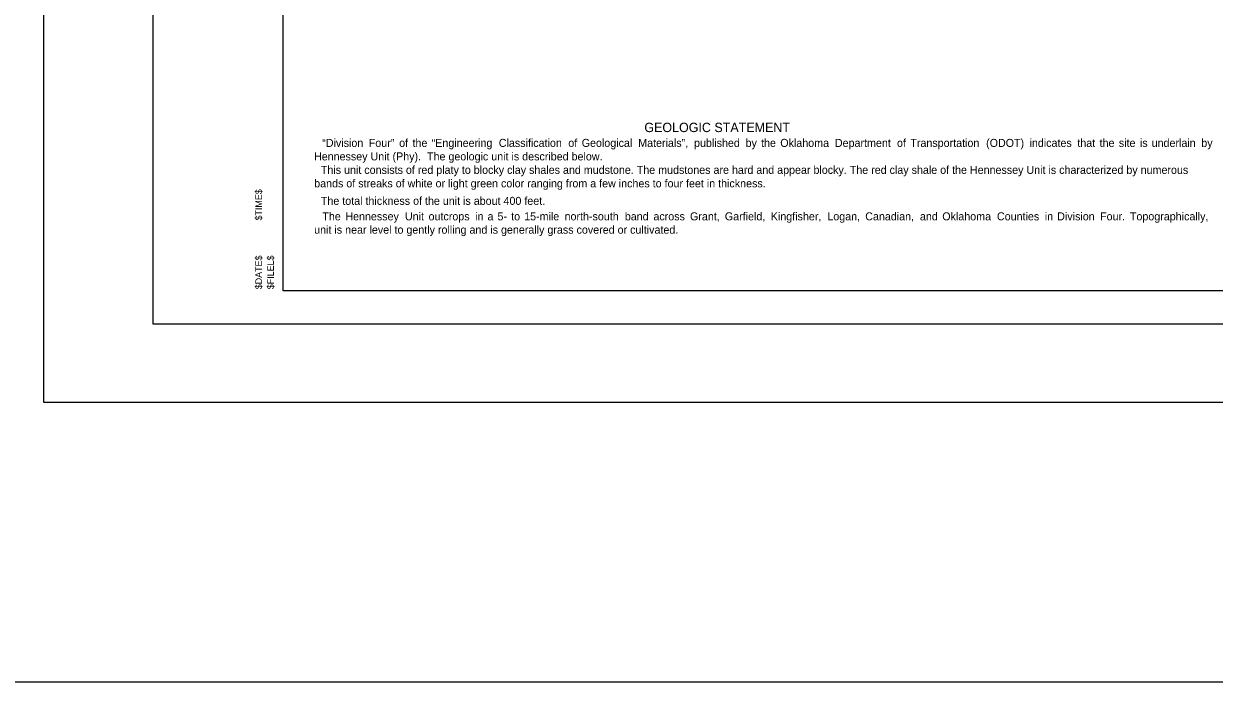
# Model space of a CAD drawing. Extents: x -6 to 173, y 24 to 64.
# Drawn here: x 6.32 to 24.17, y 25.78 to 35.64 of the extents above; entities that cross this region are included whole.
import ezdxf

# ---------------------------------------------------------------- set-up
doc = ezdxf.new("R2010")
doc.units = 0
for name, color, linetype in [('S', 7, 'Continuous'), ('SHT_Plot_Shape_Full', 7, 'Continuous'), ('SHT_Plot_Shape_Half', 7, 'Continuous'), ('SHT_Plot_Stamp', 7, 'Continuous'), ('SHT_Sheet_Border', 7, 'Continuous'), ('Text', 7, 'Continuous')]:
    doc.layers.add(name, color=color, linetype=linetype)

# ---------------------------------------------------------------- blocks, each defined once
blk = doc.blocks.new('Stamp_Plot_Stamp')
at = {"layer": 'SHT_Plot_Stamp'}
for s, p in [('$TIME$', (1.695, 1.572)), ('$DATE$', (1.695, 0.542)), ('$FILEL$', (1.873, 0.542))]:
    blk.add_text(s, height=0.1, rotation=90, dxfattribs=at).set_placement(p)

msp = doc.modelspace()

# ---------------------------------------------------------------- linework, layer by layer
at = {"layer": 'S'}
msp.add_lwpolyline([(-6.024, 64.421), (172.576, 64.421), (172.576, 25.783), (-6.024, 25.783)], close=True, dxfattribs=at)
at = {"layer": 'SHT_Plot_Shape_Full'}
msp.add_lwpolyline([(6.624, 53.971), (42.624, 53.971), (42.624, 29.971), (6.624, 29.971)], close=True, dxfattribs=at)
at = {"layer": 'SHT_Plot_Shape_Half'}
msp.add_lwpolyline([(8.262, 53.146), (42.262, 53.146), (42.262, 31.146), (8.262, 31.146)], close=True, dxfattribs=at)
at = {"layer": 'SHT_Sheet_Border'}
msp.add_lwpolyline([(10.212, 52.646), (41.712, 52.646), (41.712, 31.646), (10.212, 31.646)], close=True, dxfattribs=at)

# ---------------------------------------------------------------- block references
at = {"layer": 'SHT_Plot_Stamp'}
msp.add_blockref('Stamp_Plot_Stamp', (8.198, 31.127), dxfattribs=at)

# ---------------------------------------------------------------- texts
at = {"layer": 'Text'}
for s, height, p in [('GEOLOGIC STATEMENT', 0.14, (15.626, 34.023)), ('“Division', 0.12, (10.797, 33.801)), ('Four”', 0.12, (11.494, 33.801)), ('of', 0.12, (11.95, 33.801)), ('the', 0.12, (12.15, 33.801)), ('“Engineering', 0.12, (12.438, 33.801)), ('Classification', 0.12, (13.444, 33.801)), ('of', 0.12, (14.486, 33.801)), ('Geological', 0.12, (14.687, 33.801)), ('Materials”,', 0.12, (15.534, 33.801)), ('published', 0.12, (16.371, 33.801)), ('by', 0.12, (17.144, 33.801)), ('the', 0.12, (17.376, 33.801)), ('Oklahoma', 0.12, (17.664, 33.801)), ('Department', 0.12, (18.483, 33.801)), ('of', 0.12, (19.414, 33.801)), ('Transportation', 0.12, (19.614, 33.801)), ('(ODOT)', 0.12, (20.75, 33.801)), ('indicates', 0.12, (21.401, 33.801)), ('that', 0.12, (22.118, 33.801)), ('the', 0.12, (22.452, 33.801)), ('site', 0.12, (22.74, 33.801)), ('is', 0.12, (23.056, 33.801)), ('underlain', 0.12, (23.232, 33.801)), ('by', 0.12, (23.977, 33.801)), ('Hennessey Unit (Phy).  The geologic unit is described below.', 0.12, (10.673, 33.599)), ('  This unit consists of red platy to blocky clay shales and mudstone. The mudstones are hard and appear blocky. The red clay shale of the Hennessey Unit is characterized by numerous ', 0.12, (10.687, 33.397)), ('bands of streaks of white or light green color ranging from a few inches to four feet in thickness.', 0.12, (10.676, 33.195)), ('  The total thickness of the unit is about 400 feet.', 0.12, (10.687, 32.933)), ('The', 0.12, (10.798, 32.701)), ('Hennessey', 0.12, (11.143, 32.701)), ('Unit', 0.12, (12.037, 32.701)), ('outcrops', 0.12, (12.391, 32.701)), ('in', 0.12, (13.089, 32.701)), ('a', 0.12, (13.275, 32.701)), ('5-', 0.12, (13.424, 32.701)), ('to', 0.12, (13.629, 32.701)), ('15-mile', 0.12, (13.824, 32.701)), ('north-south', 0.12, (14.43, 32.701)), ('band', 0.12, (15.333, 32.701)), ('across', 0.12, (15.762, 32.701)), ('Grant,', 0.12, (16.311, 32.701)), ('Garfield,', 0.12, (16.833, 32.701)), ('Kingfisher,', 0.12, (17.522, 32.701)), ('Logan,', 0.12, (18.37, 32.701)), ('Canadian,', 0.12, (18.938, 32.701)), ('and', 0.12, (19.758, 32.701)), ('Oklahoma', 0.12, (20.093, 32.701)), ('Counties', 0.12, (20.913, 32.701)), ('in', 0.12, (21.63, 32.701)), ('Division', 0.12, (21.816, 32.701)), ('Four.', 0.12, (22.459, 32.701)), ('Topographically,', 0.12, (22.906, 32.701)), ('unit is near level to gently rolling and is generally grass covered or cultivated.  ', 0.12, (10.676, 32.501))]:
    msp.add_text(s, height=height, dxfattribs=at).set_placement(p)

doc.saveas('drawing.dxf')
